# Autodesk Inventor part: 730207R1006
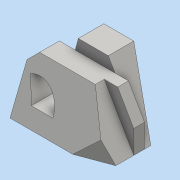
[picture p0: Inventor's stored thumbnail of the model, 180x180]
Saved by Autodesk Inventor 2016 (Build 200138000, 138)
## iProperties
Created: 2023-02
Part Number: 730207R1006
Material: 일반
Document SubType Name: Modeling
Designer: PC-1-14
Density: 1 g/cm^3
Appearance: 기본값
Author: PC-1-14
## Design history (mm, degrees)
sketch "스케치1"
  geometry: L1 (0, 0)-(-105, 0); L2 (-105, 0)-(-105, 57); L3 (-105, 57)-(0, 57); L4 (0, 57)-(0, 0)
  constraints: 8 end point, 2 parallel, 1 horizontal, 1 perpendicular
  dimensions: "d0" = 105 distance of L2.end L3.end; "d1" = 57 distance of L1.end L2.end
extrude "돌출1" new body sketch "스케치1" distance "d2" = 45; taper "d3" = 0 deg
sketch "스케치2"
  geometry: L1 (0, 0)-(105, 0) reference; L2 (105, 0)-(105, -57) reference; L3 (105, -57)-(0, -57) reference; L4 (0, -57)-(0, 0) reference; L5 (105, 0)-(64.585, -70); L6 (0, 0)-(105, 0); L7 (31.201, -70)-(17, -17); L8 (64.585, -70)-(31.201, -70); L9 (17, -17)-(17, 0); 1 further point
  constraints: 10 end point, 2 horizontal, 1 perpendicular, 1 point on line
  dimensions: "d4" = 60 deg angle of L1 L5; "d12" = 17 horizontal distance of point (0, 0) L7.end; "d13" = 70 vertical distance of L1.end L5.end; "d14" = 75 deg angle of L1 L7; "d15" = 17 horizontal distance of point (0, 0) L7.end
extrude "돌출2" join sketch "스케치2" distance "d7" = 7; taper "d8" = 0 deg
feature "면 기울기1" dims angle "d9" = 17 deg
sketch "스케치3"
  geometry: L1 (27.718, 57)-(72.091, 57) reference; L2 (72.091, 57)-(64.585, 70) reference; L3 (64.585, 70)-(105, 0) reference; L4 (105, 0)-(17, 0) reference; L5 (0, 0)-(105, 0) reference; L6 (105, 0)-(105, 57) reference; L7 (105, 57)-(0, 57) reference; L8 (0, 57)-(0, 0) reference; L9 (119.154, 1.484)-(69.103, 88.175); L10 (69.103, 88.175)-(139.676, 78.943); L11 (139.676, 78.943)-(119.154, 1.484); L12 (64.585, 70)-(31.201, 70) reference; L13 (31.201, 70)-(27.718, 57) reference; L14 (17, 0)-(17, 17) reference; L15 (17, 17)-(31.201, 70) reference; L16 (31.201, 70)-(64.585, 70) reference; L17 (17, 17)-(41, 17); L18 (17, 17)-(7.238, 38.925); A1 r 24 centre (17, 17) between (41, 17) and (7.238, 38.925); 1 further point
  constraints: 10 end point, 2 point on circle, 1 centre point, 1 coincident, 1 horizontal, 1 parallel
  dimensions: "d10" = 13 distance between parallel lines of L3 L9; "d16" = 24 distance of L14.end L17.end
  node "투영된 루프2"
  node "투영된 루프3"
  node "투영된 루프4"
extrude "돌출3" cut sketch "스케치3" stored distance "d18" = 7; taper "d19" = 0 deg
extrude "돌출4" cut sketch "스케치3" stored distance "d20" = 7; taper "d21" = 0 deg
chamfer "모따기1" distance "d22" = 10; stored, may be unused: second distance "d23" = 2, angle "d24" = 45 deg
sketch "스케치4"
  geometry: L1 (77.282, -45)-(42.282, -45); L2 (42.282, -45)-(42.282, -32); L3 (42.282, -32)-(77.282, -32); L4 (77.282, -32)-(77.282, -45); L5 (77.282, 0)-(77.282, -45) reference; L6 (59.384, 0)-(77.282, 0) reference; L7 (59.384, -45)-(59.384, 0) reference; L8 (77.282, -45)-(59.384, -45) reference; L9 (77.282, -32)-(42.282, -45); L10 (77.282, 0)-(77.282, -45) reference; L11 (77.282, -45)-(77.282, -32); L12 (77.282, -45)-(42.282, -45); 1 further point
  constraints: 14 end point, 2 parallel, 2 perpendicular, 1 collinear, 1 horizontal
  dimensions: "d25" = 35 distance of L2.end L3.end; "d26" = 13 distance of L1.start L3.end
extrude "돌출5" cut sketch "스케치4" stored distance "d27" = 7; taper "d28" = 0 deg
sketch "스케치6"
  geometry: L1 (64.585, 70)-(105, 0) reference; L2 (105, 0)-(17, 0) reference; L3 (17, 0)-(17, 17) reference; L4 (17, 17)-(31.201, 70) reference; L5 (31.201, 70)-(64.585, 70) reference; L6 (105, 0)-(72.091, 57) reference; L7 (105, 0)-(70, 0) reference; L8 (105, 26)-(105, 0) reference; L9 (87.102, 57)-(105, 26) reference; L10 (70, 57)-(87.102, 57) reference; L11 (70, 0)-(70, 57) reference; L12 (72.091, 57)-(87.102, 57) reference; L13 (72.091, 57)-(105, 0); L14 (105, 26)-(105, 0) reference; L15 (105, 26)-(105, 0); L16 (105, 26)-(87.102, 57); L17 (87.102, 57)-(72.091, 57); 1 further point
  constraints: 8 end point, 2 collinear, 1 horizontal
extrude "돌출7" cut sketch "스케치6" distance "d32" = 33; taper "d33" = 0 deg
sketch "스케치5"
  geometry: L1 (26, -32)-(26, -45) reference; L2 (-31, -45)-(-31, -44.223) reference; L3 (26, -45)-(-31, -45) reference; L4 (0, 0)-(26, 0) reference; L5 (0, 0)-(0, -12) reference; L6 (0, 0)-(0, -12) reference; L7 (-31, 0)-(0, 0) reference; L8 (-31, -12)-(-31, 0) reference; L9 (26, 0)-(-31, 0) reference; L10 (26, 0)-(26, 7) reference; L11 (-44, 28.401)-(26, 7) reference; L12 (-44, 0)-(-44, 28.401) reference; L13 (-31, 0)-(-44, 0) reference; L14 (26, -45)-(-60.672, -9.982); L15 (-60.672, -9.982)-(-21.42, -83.323); L16 (-21.42, -83.323)-(26, -45); L17 (26, -32)-(-31, -44.223) reference; L18 (0, -12)-(26, -12) reference; L19 (26, -12)-(26, 0) reference; L20 (-31, -12)-(0, -12) reference; 1 further point
  constraints: 6 end point
extrude "돌출6" cut sketch "스케치5" stored distance "d30" = 0; taper "d31" = 0 deg
sketch "스케치7"
  geometry: L1 (92.864, -21.02)-(70, 0) reference; L2 (72.091, -57)-(92.864, -21.02) reference; L3 (10, -57)-(72.091, -57) reference; L4 (0, -47)-(10, -57) reference; L5 (0, 0)-(0, -47) reference; L6 (0, 0)-(70, 0) reference; L7 (17, -17)-(41, -17) reference; L8 (7.238, -38.925)-(17, -17) reference; L9 (105, 0)-(17, 0) reference; L10 (17, -17)-(41, -17); L11 (41, -17)-(41, 0); L12 (41, 0)-(17, 0); L13 (17, 0)-(17, -17); A1 r 24 centre (17, -17) between (7.238, -38.925) and (41, -17) reference; 1 further point
  constraints: 8 end point, 2 parallel, 1 horizontal, 1 perpendicular, 1 point on line
  dimensions: "d34" = 24 distance of L10.start L10.end
extrude "돌출8" cut sketch "스케치7" distance "d35" = 33; taper "d36" = 0 deg
node "솔리드1"
node "투영된 루프1"
node "투영된 루프5"
node "투영된 루프6"
node "투영된 루프7"
node "투영된 루프8"
node "투영된 루프9"
node "투영된 루프10"
node "투영된 루프11"
node "투영된 루프12"
other parameters: "d17" = 39 deg
